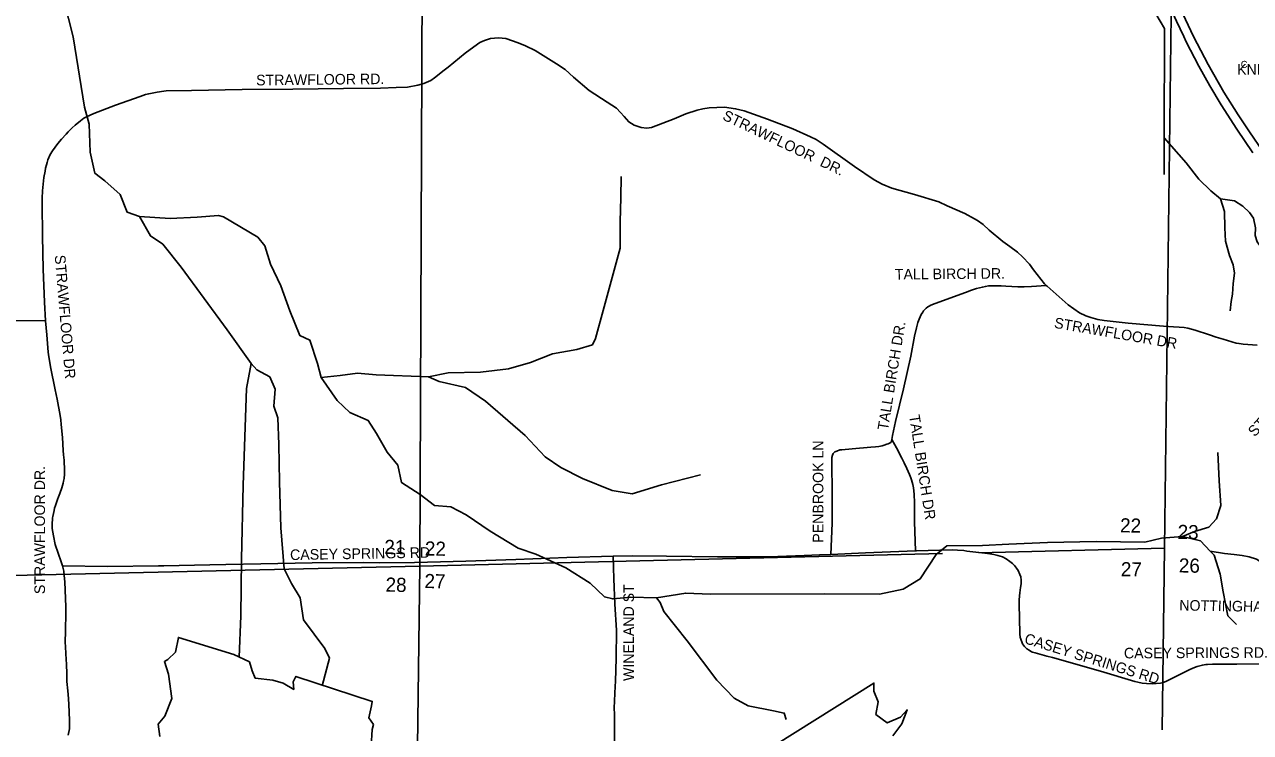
# Model space of a CAD drawing. Extents: x 1670563 to 1761545, y 515755 to 578944.
# Drawn here: x 1675065 to 1683746, y 542631 to 547646 of the extents above; entities that cross this region are included whole.
import ezdxf

# ---------------------------------------------------------------- set-up
doc = ezdxf.new("R2010")
doc.units = 0
for name, color, linetype in [('5_sectionlines', 7, 'Continuous'), ('62_text', 7, 'Continuous'), ('CEMETERY', 7, 'Continuous'), ('Cross', 7, 'Continuous'), ('SHP_LINE', 7, 'Continuous'), ('STREETCL', 7, 'Continuous'), ('STRNAMES', 7, 'Continuous')]:
    doc.layers.add(name, color=color, linetype=linetype)

msp = doc.modelspace()

# ---------------------------------------------------------------- linework, layer by layer
at = {"layer": '5_sectionlines'}
for p, q in [((1681822.7, 543903.5), (1683137.9, 543937.2)), ((1677863.7, 543809.9), (1681565.1, 543899.3))]:
    msp.add_line(p, q, dxfattribs=at)
for points in [[(1678010.6, 565035.6), (1677977.7, 559756.7), (1677931.5, 554408.9), (1677884.5, 549117.2), (1677863.7, 543809.9), (1677796.8, 538521.9), (1677728, 533231.8)], [(1683202.1, 549227.4), (1683137.9, 543937.2), (1683120.5, 542649.7)], [(1677863.7, 543809.9), (1672611, 543689.6), (1670563.1, 543670.7)]]:
    msp.add_lwpolyline(points, dxfattribs=at)
at = {"layer": 'SHP_LINE'}
for points in [[(1683138, 547618), (1683045, 547774), (1682976, 547826), (1682939, 547908), (1682949, 548018), (1682898, 548216), (1682836, 548347), (1682709, 548391), (1682610, 548525), (1682524, 548836), (1682428, 549117), (1682201, 549568), (1682074, 549801), (1682013, 549921), (1681945, 550087)], [(1675880, 546286), (1675791, 546317), (1675743, 546443), (1675633, 546538), (1675564, 546592), (1675531, 546741), (1675522, 546941), (1675489, 547060), (1675409, 547558), (1675280, 548071), (1675155, 548289), (1675122, 548408), (1675131, 548485), (1675208, 548524), (1675328, 548524), (1675477, 548557), (1675531, 548664), (1675528, 548775), (1675478, 548908)], [(1683135, 546844), (1683138, 547618)], [(1683134, 546583), (1683135, 546844)], [(1683135, 546844), (1683291, 546666), (1683379, 546551), (1683464, 546469), (1683533, 546411)], [(1677926, 545150), (1678064, 545178), (1678295, 545183), (1678491, 545206), (1678647, 545253), (1678803, 545313), (1678977, 545343), (1679086, 545378), (1679109, 545422), (1679163, 545620), (1679282, 546062), (1679282, 546249), (1679287, 546421), (1679289, 546570)], [(1683533, 546411), (1683561, 546321), (1683564, 546206), (1683570, 546112), (1683597, 546009), (1683624, 545943), (1683633, 545885), (1683624, 545812), (1683618, 545737), (1683609, 545685), (1683603, 545619)], [(1683533, 546411), (1683633, 546396), (1683691, 546360), (1683739, 546315), (1683766, 546275), (1683782, 546206), (1683779, 546151), (1683794, 546106), (1683848, 546033), (1683875, 545991), (1683906, 545961), (1683972, 545888), (1683994, 545873), (1684015, 545846), (1684066, 545806), (1684093, 545779), (1684124, 545746), (1684151, 545713), (1684175, 545670), (1684208, 545622), (1684218, 545598)], [(1675880, 546286), (1676097, 546272), (1676288, 546281), (1676438, 546293), (1676475, 546284), (1676717, 546139), (1676766, 546079), (1676807, 545949), (1676881, 545796), (1676944, 545619), (1677014, 545444), (1677086, 545411), (1677140, 545246), (1677166, 545146)], [(1676671, 545244), (1676501, 545483), (1676175, 545928), (1676044, 546090), (1675957, 546149), (1675880, 546286)], [(1676585, 543164), (1676596, 543458), (1676602, 543860), (1676614, 544384), (1676637, 545068), (1676671, 545244)], [(1677173, 542963), (1677225, 543158), (1677191, 543227), (1677041, 543429), (1677018, 543584), (1676955, 543687), (1676903, 543791), (1676881, 544081), (1676870, 544407), (1676865, 544671), (1676858, 544859), (1676830, 544943), (1676839, 545062), (1676802, 545150), (1676711, 545199), (1676671, 545244)], [(1677166, 545146), (1677301, 545160), (1677424, 545176), (1677555, 545164), (1677926, 545150)], [(1677166, 545146), (1677280, 544982), (1677369, 544898), (1677499, 544842), (1677558, 544749), (1677632, 544616), (1677709, 544525), (1677735, 544402), (1677866, 544316), (1677969, 544239), (1678085, 544230), (1678193, 544174), (1678363, 544058), (1678561, 543937), (1678685, 543895), (1678897, 543797), (1679071, 543690), (1679172, 543592), (1679230, 543578), (1679358, 543590), (1679541, 543584)], [(1679851, 544457), (1679576, 544385), (1679368, 544322), (1679226, 544345), (1679017, 544431), (1678863, 544508), (1678751, 544583), (1678611, 544734), (1678330, 544977), (1678188, 545075), (1678002, 545117), (1677926, 545150)], [(1683514, 544615), (1683524, 544415), (1683535, 544240), (1683505, 544145), (1683451, 544086), (1683349, 544054), (1683265, 544020)], [(1679541, 543584), (1679747, 543619), (1679921, 543610), (1680728, 543614), (1681118, 543610), (1681286, 543647), (1681407, 543719), (1681521, 543891), (1681596, 543954), (1681849, 543955), (1682035, 543966), (1682308, 543978), (1682653, 543983), (1682997, 543980), (1683116, 544008), (1683265, 544020), (1683391, 543989), (1683461, 543916)], [(1683461, 543916), (1683562, 543899), (1683630, 543891), (1683686, 543884), (1683736, 543875), (1683789, 543860), (1683884, 543797), (1683922, 543737), (1683966, 543681)], [(1683461, 543916), (1683489, 543887), (1683531, 543752), (1683552, 543628), (1683586, 543458), (1683647, 543396)], [(1680459, 542724), (1680444, 542769), (1680369, 542784), (1680189, 542820), (1680090, 542874), (1679967, 543002), (1679757, 543281), (1679592, 543488), (1679565, 543551), (1679541, 543584)], [(1677519, 542535), (1677527, 542652), (1677536, 542689), (1677504, 542736), (1677522, 542820), (1677527, 542852), (1676987, 543029), (1676967, 542991), (1676972, 542936), (1676897, 542980), (1676824, 543003), (1676699, 543015), (1676676, 543067), (1676658, 543131), (1676547, 543183), (1676155, 543305), (1676134, 543201), (1676079, 543149), (1676056, 543134), (1676085, 543044), (1676108, 542873), (1676059, 542748), (1676012, 542690), (1676024, 542603)], [(1680243, 542456), (1681080, 542981), (1681080, 542923), (1681110, 542849), (1681094, 542759), (1681174, 542699), (1681268, 542739), (1681314, 542793), (1681276, 542693), (1681214, 542607)]]:
    msp.add_lwpolyline(points, dxfattribs=at)
at = {"layer": 'STREETCL'}
for points in [[(1683834.5, 546745.2), (1683737.6, 546884.7), (1683657.9, 547005.3), (1683557.2, 547167.2), (1683445.2, 547362.6), (1683341.6, 547561.1), (1683248.4, 547760.8), (1683163.1, 547960.4), (1683086.8, 548160.4), (1683020.3, 548358.6), (1682960.9, 548556.1), (1682904.1, 548755), (1682846.9, 548954.6), (1682790, 549152.8), (1682716, 549409.4), (1682648.1, 549646.8)], [(1683762.8, 546737.1), (1683648.3, 546903.8), (1683538.5, 547077.1), (1683457.9, 547212.3), (1683380, 547351.7), (1683291, 547524.1), (1683273.1, 547560.4), (1683220.9, 547669.6), (1683156.6, 547813.7), (1683050.2, 548075.4), (1682973.7, 548296.8), (1682925.1, 548454.5), (1682862.7, 548670.5), (1682783.8, 548948.7), (1682750.8, 549062.1), (1682701.1, 549236), (1682692.7, 549265)], [(1675213.9, 545547.7), (1675207.1, 545680.2), (1675197.5, 545913.2), (1675192, 546147.1), (1675190.8, 546378.9), (1675190.8, 546415.4), (1675193.3, 546466.9), (1675202.5, 546562.9), (1675210.5, 546607.8), (1675214.3, 546628.7), (1675220.1, 546651.3), (1675224.8, 546668.9), (1675231.5, 546687.8), (1675247.4, 546724.3), (1675263.8, 546752.4), (1675300.7, 546802.7), (1675326.3, 546834.1), (1675360.1, 546870.1), (1675374.7, 546884.8), (1675403.7, 546913.7), (1675423.8, 546932.1), (1675461.6, 546964.8), (1675484.6, 546981.6), (1675503.5, 546992.9), (1675555.1, 547014.7), (1675710, 547074.8), (1675884.8, 547136.9), (1675921.7, 547149.5), (1675945.2, 547155.8), (1676005, 547166.8), (1676051.2, 547173.5), (1676068.4, 547175.6), (1676246.6, 547178.1), (1676606.4, 547185.6), (1676964.6, 547189), (1677324.4, 547193.2), (1677585.3, 547194.8), (1677695.9, 547198.7), (1677777.7, 547203.3), (1677850.7, 547215.8), (1677893.1, 547227.2), (1677941.6, 547249.1), (1677969.3, 547268.4), (1678036, 547321.6), (1678065.1, 547344), (1678184.7, 547443.4), (1678246.9, 547487.8), (1678289.7, 547518), (1678321.6, 547531.8), (1678365.2, 547546), (1678420.5, 547552.3), (1678473, 547547.3), (1678560.6, 547517), (1678611.7, 547494.8), (1678681.8, 547462.1), (1678832.8, 547366.5), (1678893.5, 547327.1), (1678953.5, 547273.5), (1679063.4, 547177.9), (1679191.6, 547097.1), (1679257, 547053.9), (1679284.7, 547023.7), (1679312, 546993.6), (1679343.7, 546956.2), (1679382.8, 546932.3), (1679430.6, 546916.8), (1679470.8, 546911.7), (1679503.5, 546916.8), (1679664.2, 546978.8), (1679748.5, 547012.4), (1679828.6, 547038.4), (1679868.4, 547048.1), (1679912.9, 547055.2), (1680022.4, 547059.4), (1680099.5, 547048.9), (1680161.1, 547033.4), (1680326.4, 546974.7), (1680504.2, 546907.8), (1680631.3, 546849.9), (1680671.4, 546830.8), (1680720.1, 546799.4), (1680941.5, 546641), (1681081.1, 546546.2), (1681136.9, 546514.4), (1681205.7, 546487.6), (1681366.7, 546442.4), (1681539.9, 546389.2), (1681598.6, 546361.8), (1681724, 546306.4), (1681792.8, 546270), (1681812.5, 546257), (1681852, 546228.5), (1681895.2, 546188.7), (1681993.3, 546108.2), (1682041.5, 546074.7), (1682095.2, 546034.5), (1682132.5, 546001.4), (1682180.2, 545947.8), (1682209.9, 545907.9), (1682287.5, 545809.8), (1682299.2, 545798.5)], [(1681206.8, 544707.3), (1681211, 544734.3), (1681231.8, 544834.4), (1681287.8, 545064.9), (1681340.1, 545296.4), (1681367.2, 545439.1), (1681380.1, 545498.1), (1681390.8, 545534.6), (1681398.7, 545559.9), (1681414.4, 545593.1), (1681425.1, 545607.7), (1681431.4, 545617.3), (1681439.9, 545627.9), (1681450, 545636.9), (1681461.2, 545645.4), (1681470.3, 545651.6), (1681482.1, 545657.7), (1681512.4, 545670.7), (1681729, 545747.1), (1681769.5, 545763.6), (1681806.1, 545775.9), (1681847.7, 545786.6), (1681868.5, 545790.6), (1681891, 545793.9), (1681920.3, 545796.2), (1681933.8, 545795.6), (1681955.7, 545795.1), (1681979.4, 545793.9), (1682012.5, 545792.2), (1682097.5, 545788.9), (1682143.5, 545788.8), (1682194.1, 545790), (1682299.2, 545798.5)], [(1682299.2, 545798.5), (1682305.6, 545792.2), (1682454.7, 545661.1), (1682535.2, 545603.3), (1682579.1, 545582.8), (1682614.8, 545570.3), (1682666, 545556.9), (1682710.8, 545549.7), (1682817, 545538), (1682880.3, 545531.7), (1683129, 545509.8), (1683201.1, 545505.6), (1683241.3, 545502.3), (1683277, 545499.7), (1683303, 545495.6), (1683353.7, 545481.7), (1683454.8, 545447.8), (1683502.1, 545432.6), (1683552.4, 545416.2), (1683645.1, 545389.7), (1683665.5, 545385.8), (1683693.2, 545382.4), (1683793.4, 545374.4)], [(1675213.8, 545547.9), (1675001.1, 545549), (1674838.6, 545549), (1674644, 545549.9), (1674447.5, 545551.7), (1674266.1, 545554.3)], [(1675333.4, 543811.8), (1675325.8, 543840.5), (1675303.9, 543901), (1675283.5, 543963.6), (1675270.8, 544023.6), (1675262.1, 544076), (1675262.1, 544120.8), (1675262.6, 544133.5), (1675264.2, 544150.8), (1675266.2, 544160.5), (1675274.8, 544204.2), (1675277.5, 544220), (1675283.9, 544238.1), (1675294.3, 544267.2), (1675298.2, 544281.2), (1675305, 544301.4), (1675314.2, 544323.2), (1675328.4, 544363.8), (1675334.3, 544381.8), (1675339, 544398.1), (1675341.1, 544412.4), (1675345.3, 544431.2), (1675347.4, 544460.2), (1675347.8, 544503.8), (1675345.7, 544543.2), (1675345.7, 544559.9), (1675341.9, 544597.2), (1675339.8, 544629.5), (1675333.1, 544720.9), (1675325.9, 544813.5), (1675323.4, 544847), (1675318.8, 544876.3), (1675296.5, 544992.5), (1675281.8, 545059.4), (1675249.5, 545220.4), (1675236.1, 545308), (1675233.6, 545325.2), (1675222.3, 545448.8), (1675213.9, 545547.7)], [(1680773.5, 543892.8), (1680782.7, 544114.7), (1680783.6, 544394), (1680782, 544476), (1680782, 544557.5), (1680782, 544579.5), (1680785.9, 544595.8), (1680791.5, 544608.1), (1680802.2, 544618.3), (1680816.8, 544625), (1680837.7, 544632.3), (1680852.8, 544634.6), (1680924.3, 544641.3), (1681058, 544651.7), (1681091.7, 544655), (1681114.3, 544657.3), (1681138.4, 544661.8), (1681152.5, 544665.7), (1681170.5, 544673), (1681180.1, 544677), (1681198.1, 544686.5), (1681204.3, 544695.5), (1681206, 544701.7), (1681206.8, 544707.3)], [(1681374.6, 543916.9), (1681367.9, 544123.5), (1681367.5, 544258.6), (1681365.4, 544320.1), (1681359.3, 544364.8), (1681357.3, 544376), (1681354.3, 544388.7), (1681346.1, 544421.7), (1681341, 544434.4), (1681331.9, 544457.8), (1681312.5, 544501), (1681293.2, 544541.7), (1681276.9, 544574.8), (1681238.8, 544648), (1681206.8, 544707.3)], [(1680773.5, 543892.8), (1681019.3, 543902.8), (1681374.6, 543916.9)], [(1681374.6, 543916.9), (1681381.5, 543917.2), (1681545.6, 543922.8), (1681632.8, 543924.5), (1681670.9, 543923.4), (1681716.2, 543920.1), (1681738.3, 543916.8), (1681865.9, 543901.5), (1681900.1, 543897.7), (1681927.7, 543892.7), (1681957, 543886.1), (1681990.7, 543875), (1682016.1, 543860.7), (1682042.4, 543843.3), (1682060.1, 543827.9), (1682075.6, 543813), (1682089.4, 543794.7), (1682100.4, 543777.6), (1682113.1, 543750.6), (1682119.8, 543732.9), (1682121.4, 543710.3), (1682122, 543683.2), (1682117.6, 543657.8), (1682112.6, 543621.4), (1682110.9, 543599.3), (1682108.7, 543569.6), (1682107.1, 543541.9), (1682112.6, 543331.6), (1682114.8, 543302.3), (1682116.5, 543298.5), (1682131.3, 543258.7), (1682145.7, 543239.4), (1682162.3, 543222.8), (1682177.7, 543213.4), (1682194.9, 543203.5), (1682203.1, 543200.7), (1682221.4, 543194.7), (1682303.7, 543172.6), (1682342.9, 543162.1), (1682684.2, 543064.7), (1682926.6, 542992.8), (1682947, 542988.4), (1682977.9, 542981.2), (1683010.5, 542977.9), (1683049.1, 542975.5), (1683109.3, 542981.1), (1683127.5, 542986), (1683146.9, 542992.7), (1683311.7, 543075.4), (1683338.2, 543087.5), (1683368.5, 543099.1), (1683405, 543109.1), (1683430.4, 543112.4), (1683442, 543113.5), (1683477.9, 543114.6), (1683647.9, 543116.2), (1683975.3, 543117.4)], [(1675333.4, 543811.8), (1675652.9, 543808.1), (1676014.1, 543811.4), (1676052.2, 543812), (1676377.5, 543818.1), (1676490.7, 543820.3), (1676737.6, 543825.3), (1677101, 543831.9), (1677463.8, 543834.7), (1677580.9, 543833.6), (1677827.2, 543836.4), (1678011.1, 543839.7), (1678189.5, 543845.8), (1678543, 543856.3), (1678904.1, 543870.8), (1679234.2, 543879.8)], [(1679234.2, 543879.8), (1679237.6, 543718.7), (1679244.6, 543539.9), (1679257.2, 543355.9), (1679255, 543157.5), (1679248.6, 542993.1), (1679248.2, 542958.6), (1679241.1, 542803.3), (1679241.5, 542760.7), (1679243.8, 542560.4), (1679246, 542361.5), (1679245.3, 542163.7), (1679245.6, 541964.4), (1679243.1, 541912), (1679239.9, 541894), (1679230.2, 541864.6), (1679211.1, 541835.5), (1679200.7, 541826.5), (1679186.7, 541818.3), (1679173.8, 541813.2), (1679143.3, 541809.3), (1679055.3, 541810.4), (1678831.5, 541813.1), (1678733.4, 541811.2)], [(1679234.2, 543879.8), (1679371.3, 543881.9), (1679610.5, 543880.2), (1679972.8, 543876.3), (1680335, 543875.7), (1680585.8, 543885.1), (1680693.5, 543889.5), (1680773.5, 543892.8)], [(1675333.4, 543811.8), (1675343.1, 543774.8), (1675347.2, 543743.8), (1675350.8, 543698.1), (1675357.9, 543520.5), (1675358.4, 543478.9), (1675354.4, 543350.7), (1675353.9, 543268.8), (1675355.4, 543240.9), (1675357.5, 543189.5), (1675362.5, 543112.1), (1675365.1, 543050.1), (1675366.1, 542991.7), (1675371.2, 542927.1), (1675376.3, 542872.9), (1675380.4, 542780.8), (1675384.4, 542712.1), (1675384.9, 542690.9), (1675382.9, 542658.3), (1675373.7, 542613)]]:
    msp.add_lwpolyline(points, dxfattribs=at)

# ---------------------------------------------------------------- texts
at = {"layer": '62_text'}
for s, rotation, p in [('22', 358.93026, (1682821.7, 544049.1)), ('23', 358.93024, (1683229, 544002.7)), ('21', 358.93111, (1677612.2, 543896.5)), ('22', 358.93111, (1677899.3, 543885.1)), ('27', 358.93114, (1682826.8, 543738.6)), ('26', 358.93109, (1683237.8, 543765.2)), ('27', 358.93114, (1677896.5, 543654.6)), ('28', 358.93114, (1677620.8, 543629.2))]:
    msp.add_text(s, height=100, rotation=rotation, dxfattribs=at).set_placement(p)
at = {"layer": 'CEMETERY'}
msp.add_text('KNIGHTS OF', height=75, dxfattribs=at).set_placement((1683651.2, 547290.2))
at = {"layer": 'Cross'}
msp.add_text('C', height=50, dxfattribs=at).set_placement((1683676.7, 547338.5))
at = {"layer": 'STRNAMES'}
for s, rotation, p in [('STRAWFLOOR RD.', 0.614, (1676705.4, 547214.5)), ('STRAWFLOOR  DR.', 334.56517, (1680001.7, 546975.3)), ('STRAWFLOOR DR', 274.80744, (1675278.9, 546010.9)), ('TALL BIRCH DR.', 0.4788, (1681228, 545839.5)), ('STRAWFLOOR DR', 350.22328, (1682352.2, 545498)), ('TALL BIRCH DR.', 80.75371, (1681178.3, 544767.7)), ('STRAWFLOOR DRIVE', 47.06657, (1683775.4, 544721.6)), ('TALL BIRCH DR', 278.8108, (1681328.6, 544876.6)), ('PENBROOK LN', 90, (1680721.7, 543975.4)), ('STRAWFLOOR DR.', 90, (1675210.5, 543611.4)), ('CASEY SPRINGS RD', 1.00215, (1676946.1, 543852.5)), ('WINELAND ST', 90, (1679380.6, 542996.3)), ('NOTTINGHAM WAY', 358.99843, (1683241, 543495.9)), ('CASEY SPRINGS RD', 342.78475, (1682139.2, 543264.9)), ('CASEY SPRINGS RD.', 0.25843, (1682849.8, 543156.1))]:
    msp.add_text(s, height=75, rotation=rotation, dxfattribs=at).set_placement(p)

doc.saveas('drawing.dxf')
